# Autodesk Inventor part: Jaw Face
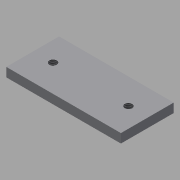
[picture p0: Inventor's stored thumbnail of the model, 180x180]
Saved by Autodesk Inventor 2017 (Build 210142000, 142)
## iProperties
Shininess: 77.0
Length Units: 11269
Angle Units: 11279
Time Units: 11290
Mass Units: 11283
Length Display Precision: 3
Angle Display Precision: 2
Compacted: True
Created: 2002-02
Part Number: Jaw Face
Document SubType Name: Modeling
Designer: ***
Density: 1 g/cm^3
Material: Generic
Mass: 15.6207 g
Surface Area: 67.651 cm^2
Volume: 15.6207 cm^3
Appearance: Default
Density: 0.0
Volumn: 0.0
Area: 0.0
PropertySet Name: Model Information
Control State: 0
Master: False
Checked Out: False
Author: ***
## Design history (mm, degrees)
sketch "Sketch1"
  geometry: L1 (-79.661, -8.43)-(-3.661, -8.43); L2 (-3.661, -8.43)-(-3.661, -43.43); L3 (-3.661, -43.43)-(-79.661, -43.43); L4 (-79.661, -43.43)-(-79.661, -8.43)
  constraints: 8 end point, 2 parallel, 1 horizontal, 1 perpendicular
  dimensions: "d0" = 76 distance of L2.end L3.end; "d3" = 35 distance of L1.end L2.end
extrude "Extrusion1" new body sketch "Sketch1" stored distance "d7" = 6; taper "d8" = 0 deg
hole "Hole1" diameter "d11" = 4.917; stored, may be unused: countersink angle "d15" = 90 deg, drill point angle "d17" = 118 deg; dims "d9" = 13, "d10" = 18, "d12" = 12, "d13" = 4, "d14" = 2, "d16" = 17.1
pattern_linear "Rectangular Pattern1" dims "d20" = -50
body "Solid1"
